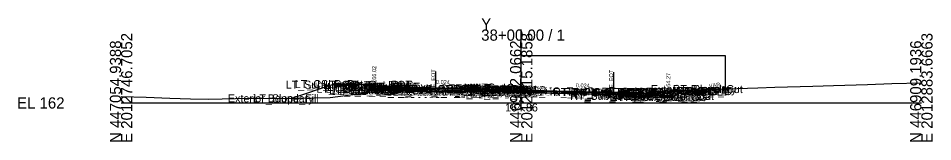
# Model space of a CAD drawing. Extents: x -26 to 3203, y -10 to 9532.
# Drawn here: x 2974.3 to 3202.8, y 1990.3 to 2021.2 of the extents above; entities that cross this region are included whole.
import ezdxf

# ---------------------------------------------------------------- set-up
doc = ezdxf.new("R2010")
doc.units = 0
for name, color, linetype in [('Default', 7, 'Continuous'), ('Exist CMT Pavement', 7, 'Continuous'), ('Exist Cross Section Cell', 7, 'Continuous'), ('Exist XS Center Line Elevation Label', 7, 'Continuous'), ('Exist XS Ground Line', 7, 'Continuous'), ('Prop CMT Conc Surface', 7, 'Continuous'), ('Prop CMT Concrete Structures', 7, 'Continuous'), ('Prop CMT Pvmt Course 1', 7, 'Continuous'), ('Prop CMT Pvmt Course 1 CG', 7, 'Continuous'), ('Prop CMT Pvmt Course 1 Wedge', 7, 'Continuous'), ('Prop CMT Pvmt Course 2', 7, 'Continuous'), ('Prop CMT Pvmt Course 2 Wedge', 7, 'Continuous'), ('Prop CMT Pvmt Course 3', 7, 'Continuous'), ('Prop CMT Pvmt Course 3 Wedge', 7, 'Continuous'), ('Prop CMT Pvmt Surface', 7, 'Continuous'), ('Prop CMT Pvmt Wedge Surface 1', 7, 'Continuous'), ('Prop CMT Pvmt Wedge Surface 2', 7, 'Continuous'), ('Prop CMT Pvmt Wedge Surface 3', 7, 'Continuous'), ('Prop CMT Slope Grass', 7, 'Continuous'), ('Prop CMT Subgrade Earthwork', 7, 'Continuous'), ('Prop XS Finish Grade CurbGutter', 7, 'Continuous'), ('Prop XS Hydro Elevations', 7, 'Continuous'), ('Prop XS Label Text', 7, 'Continuous'), ('Prop XS SE Text', 7, 'Continuous'), ('Prop XS Side Slope Text', 7, 'Continuous'), ('Scratch_Level_0', 7, 'Continuous'), ('Scratch_Level_1', 7, 'Continuous')]:
    doc.layers.add(name, color=color, linetype=linetype)

msp = doc.modelspace()

# ---------------------------------------------------------------- linework, layer by layer
at = {"layer": 'Exist CMT Pavement'}
msp.add_lwpolyline([(3078.61, 2002.84), (3080.82, 2002.84), (3081.52, 2002.84), (3082.19, 2002.84), (3084.44, 2002.85), (3085.61, 2002.85), (3088.05, 2002.86), (3088.93, 2002.86), (3091.69, 2002.86), (3092.4, 2002.86), (3093.85, 2002.86), (3095.41, 2002.86), (3095.88, 2002.86), (3097.36, 2002.86), (3099.69, 2002.86), (3100, 2002.86), (3102.21, 2002.86), (3102.77, 2002.87), (3104.5, 2002.88), (3106.34, 2002.87), (3108.04, 2002.87), (3109.85, 2002.88), (3110.18, 2002.88), (3110.83, 2002.88), (3113.06, 2002.88), (3113.64, 2002.87), (3116.47, 2002.81), (3117.27, 2002.8), (3119.89, 2002.76), (3120.9, 2002.75), (3122.11, 2002.74), (3122.7, 2002.72), (3123.07, 2002.71)], dxfattribs=at)
at = {"layer": 'Exist Cross Section Cell'}
for p, q in [((3100, 2000), (3100, 2018.35)), ((3000, 2000), (3100, 2000)), ((3100, 2000), (3200, 2000))]:
    msp.add_line(p, q, dxfattribs=at)
at = {"layer": 'Exist XS Ground Line'}
msp.add_lwpolyline([(3000, 2001.58), (3006.27, 2001.42), (3012.19, 2001.22), (3017.37, 2001), (3021.88, 2000.95), (3031.97, 2001.15), (3035.6, 2001.19), (3040.92, 2001.1), (3048.27, 2001.29), (3052.24, 2001.36), (3058, 2002.11), (3066.43, 2003.25), (3070.46, 2003.26), (3074.7, 2003.3), (3076.17, 2003.3), (3076.81, 2002.69), (3078.61, 2002.84), (3080.82, 2002.84), (3081.52, 2002.84), (3082.19, 2002.84), (3084.44, 2002.85), (3085.61, 2002.85), (3088.05, 2002.86), (3088.93, 2002.86), (3091.69, 2002.86), (3092.4, 2002.86), (3093.85, 2002.86), (3095.41, 2002.86), (3095.88, 2002.86), (3097.36, 2002.86), (3099.69, 2002.86), (3100, 2002.86), (3102.21, 2002.86), (3102.77, 2002.87), (3104.5, 2002.88), (3106.34, 2002.87), (3108.04, 2002.87), (3109.85, 2002.88), (3110.18, 2002.88), (3110.83, 2002.88), (3113.06, 2002.88), (3113.64, 2002.87), (3116.47, 2002.81), (3117.27, 2002.8), (3119.89, 2002.76), (3120.9, 2002.75), (3122.11, 2002.74), (3122.7, 2002.72), (3123.07, 2002.71), (3124.44, 2002.64), (3124.94, 2002.61), (3125.56, 2003.08), (3127.58, 2003.16), (3129.46, 2003.24), (3132.87, 2003.37), (3133.37, 2002.87), (3142.71, 2003.24), (3147.05, 2003.41), (3148.81, 2003.48), (3159.12, 2003.79), (3163.41, 2003.91), (3172.84, 2004.2), (3178.02, 2004.35), (3186.57, 2004.64), (3192.62, 2004.84), (3200, 2004.99)], dxfattribs=at)
at = {"layer": 'Prop CMT Conc Surface'}
for points in [[(3058.75, 2004.61), (3053.75, 2004.71)], [(3063.25, 2004.02), (3063.25, 2004.52), (3062.75, 2004.52)], [(3065.25, 2004.05), (3063.25, 2004.02)], [(3134.75, 2002.39), (3136.75, 2002.27)], [(3136.75, 2002.27), (3136.75, 2002.77), (3137.25, 2002.77)], [(3141.25, 2002.86), (3146.25, 2002.96)]]:
    msp.add_lwpolyline(points, dxfattribs=at)
at = {"layer": 'Prop CMT Concrete Structures'}
for points in [[(3053.75, 2004.37), (3053.75, 2004.71)], [(3053.75, 2004.71), (3058.75, 2004.61)], [(3058.75, 2004.27), (3053.75, 2004.37)], [(3058.75, 2004.61), (3058.75, 2004.27)], [(3065.25, 2004.05), (3063.25, 2004.02), (3063.25, 2004.52), (3062.75, 2004.52)], [(3062.75, 2004.52), (3062.75, 2003.53), (3065.25, 2003.47)], [(3065.25, 2003.47), (3065.25, 2004.05)], [(3096, 2003.32), (3095.99, 2003.48), (3095.24, 2003.73), (3094, 2003.85), (3092.76, 2003.83), (3092.01, 2003.58), (3092, 2003.41)], [(3092, 2003.41), (3096, 2003.32)], [(3134.75, 2002.39), (3136.75, 2002.27), (3136.75, 2002.77), (3137.25, 2002.77)], [(3137.25, 2002.77), (3137.25, 2001.75), (3134.75, 2001.81)], [(3134.75, 2001.81), (3134.75, 2002.39)], [(3146.25, 2002.96), (3141.25, 2002.86)], [(3141.25, 2002.86), (3141.25, 2002.52)], [(3141.25, 2002.52), (3146.25, 2002.62)], [(3146.25, 2002.62), (3146.25, 2002.96)]]:
    msp.add_lwpolyline(points, dxfattribs=at)
at = {"layer": 'Prop CMT Pvmt Course 1'}
for points in [[(3092, 2003.41), (3065.25, 2004.05)], [(3065.25, 2004.05), (3065.25, 2003.8)], [(3065.25, 2003.8), (3078.61, 2003.48)], [(3088.93, 2003.36), (3092, 2003.29)], [(3092, 2003.41), (3096, 2003.32)], [(3092, 2003.16), (3092, 2003.41)], [(3092, 2003.16), (3092, 2003.41)], [(3092, 2003.29), (3092, 2003.16), (3092, 2003.16)], [(3096, 2003.07), (3092, 2003.16)], [(3096, 2003.32), (3096, 2003.07)], [(3096, 2003.32), (3134.75, 2002.39)], [(3096, 2003.07), (3096, 2003.32)], [(3096, 2003.19), (3096, 2003.07), (3096, 2003.07)], [(3110.18, 2002.85), (3109.12, 2002.88)], [(3110.18, 2002.73), (3110.18, 2002.85)], [(3134.75, 2002.14), (3123.07, 2002.42)], [(3134.75, 2002.39), (3134.75, 2002.14)]]:
    msp.add_lwpolyline(points, dxfattribs=at)
at = {"layer": 'Prop CMT Pvmt Course 1 CG'}
for points in [[(3065.25, 2003.47), (3062.25, 2003.54), (3061.92, 2003.21)], [(3061.92, 2003.21), (3065.25, 2003.13)], [(3065.25, 2003.13), (3065.25, 2003.47)], [(3134.75, 2001.81), (3137.75, 2001.74), (3138.09, 2001.4)], [(3134.75, 2001.48), (3134.75, 2001.81)], [(3138.09, 2001.4), (3134.75, 2001.48)]]:
    msp.add_lwpolyline(points, dxfattribs=at)
at = {"layer": 'Prop CMT Pvmt Course 1 Wedge'}
for points in [[(3092, 2003.29), (3078.61, 2003.61)], [(3109.12, 2002.88), (3110.18, 2002.85)]]:
    msp.add_lwpolyline(points, dxfattribs=at)
at = {"layer": 'Prop CMT Pvmt Course 2'}
for points in [[(3078.61, 2003.48), (3065.25, 2003.8)], [(3065.25, 2003.8), (3065.25, 2003.47)], [(3065.25, 2003.47), (3078.61, 2003.15)], [(3092, 2003.16), (3096, 2003.07)], [(3110.18, 2002.4), (3110.18, 2002.73)], [(3110.18, 2002.73), (3123.07, 2002.42)], [(3134.75, 2001.81), (3123.07, 2002.09)], [(3134.75, 2002.14), (3134.75, 2001.81)]]:
    msp.add_lwpolyline(points, dxfattribs=at)
at = {"layer": 'Prop CMT Pvmt Course 2 Wedge'}
for points in [[(3092, 2003.16), (3088.93, 2003.24)], [(3096, 2003.07), (3104.16, 2002.87)]]:
    msp.add_lwpolyline(points, dxfattribs=at)
at = {"layer": 'Prop CMT Pvmt Course 3'}
for points in [[(3078.61, 2003.15), (3065.25, 2003.47)], [(3065.25, 2003.47), (3065.25, 2003.13)], [(3065.25, 2003.13), (3078.61, 2002.81)], [(3110.18, 2002.4), (3123.07, 2002.09)], [(3134.75, 2001.48), (3123.07, 2001.76)], [(3134.75, 2001.81), (3134.75, 2001.48)]]:
    msp.add_lwpolyline(points, dxfattribs=at)
at = {"layer": 'Prop CMT Pvmt Course 3 Wedge'}
msp.add_lwpolyline([(3090.63, 2002.86), (3088.93, 2002.9)], dxfattribs=at)
at = {"layer": 'Prop CMT Pvmt Surface'}
for points in [[(3092, 2003.41), (3065.25, 2004.05)], [(3092, 2003.41), (3096, 2003.32)], [(3096, 2003.32), (3134.75, 2002.39)]]:
    msp.add_lwpolyline(points, dxfattribs=at)
at = {"layer": 'Prop CMT Pvmt Wedge Surface 1'}
for points in [[(3065.25, 2003.8), (3065.25, 2004.05)], [(3088.93, 2003.24), (3065.25, 2003.8)], [(3092, 2003.29), (3088.93, 2003.36)], [(3088.93, 2003.36), (3088.93, 2003.24)], [(3092, 2003.41), (3092, 2003.16), (3092, 2003.16), (3092, 2003.29)], [(3096, 2003.32), (3096, 2003.07), (3096, 2003.07), (3096, 2003.19)], [(3109.12, 2002.88), (3110.18, 2002.85)], [(3110.18, 2002.85), (3110.18, 2002.73)], [(3110.18, 2002.73), (3123.07, 2002.42)], [(3134.75, 2002.14), (3134.75, 2002.39)]]:
    msp.add_lwpolyline(points, dxfattribs=at)
at = {"layer": 'Prop CMT Pvmt Wedge Surface 2'}
msp.add_line((3096, 2003.07), (3123.07, 2002.42), dxfattribs=at)
for points in [[(3065.25, 2003.8), (3065.25, 2004.05)], [(3088.93, 2003.24), (3065.25, 2003.8)], [(3092, 2003.41), (3092, 2003.16)], [(3096, 2003.32), (3096, 2003.07)], [(3096, 2003.07), (3104.16, 2002.87)], [(3134.75, 2002.14), (3134.75, 2002.39)]]:
    msp.add_lwpolyline(points, dxfattribs=at)
at = {"layer": 'Prop CMT Pvmt Wedge Surface 3'}
for p, q in [((3088.93, 2002.9), (3092, 2002.83)), ((3092, 2002.83), (3123.07, 2002.09))]:
    msp.add_line(p, q, dxfattribs=at)
for points in [[(3065.25, 2003.47), (3065.25, 2004.05)], [(3088.93, 2002.9), (3065.25, 2003.47)], [(3096, 2002.73), (3123.07, 2002.09)], [(3134.75, 2001.81), (3134.75, 2002.39)]]:
    msp.add_lwpolyline(points, dxfattribs=at)
at = {"layer": 'Prop CMT Slope Grass'}
for points in [[(3062.75, 2004.52), (3053.25, 2004.71), (3042.55, 2001.14)], [(3137.25, 2002.77), (3146.25, 2002.95)], [(3146.25, 2002.95), (3146.75, 2002.96), (3150.33, 2003.52)], [(3150.33, 2003.52), (3150.33, 2002.55), (3151, 2002.55), (3151, 2003.54)]]:
    msp.add_lwpolyline(points, dxfattribs=at)
at = {"layer": 'Prop CMT Subgrade Earthwork'}
for p, q in [((3078.61, 2002.81), (3078.61, 2002.84)), ((3123.07, 2001.76), (3123.07, 2002.71))]:
    msp.add_line(p, q, dxfattribs=at)
for points in [[(3065.25, 2003.13), (3061.92, 2003.21), (3060.58, 2004.56)], [(3078.61, 2002.81), (3065.25, 2003.13)], [(3134.75, 2001.48), (3138.09, 2001.4), (3139.51, 2002.81)], [(3123.07, 2001.76), (3134.75, 2001.48)]]:
    msp.add_lwpolyline(points, dxfattribs=at)
at = {"layer": 'Prop XS Finish Grade CurbGutter'}
for p, q in [((3150.33, 2004.04), (3150.53, 2004.04)), ((3150.33, 2004.04), (3151, 2004.04)), ((3150.33, 2004.04), (3150.33, 2003.05)), ((3150.33, 2003.05), (3150.33, 2002.55)), ((3150.33, 2003.05), (3151, 2003.05)), ((3150.33, 2002.55), (3151, 2002.55)), ((3151, 2003.63), (3150.65, 2003.99)), ((3151, 2003.63), (3151, 2003.05)), ((3151, 2003.54), (3151, 2003.54)), ((3151, 2003.05), (3151, 2002.55))]:
    msp.add_line(p, q, dxfattribs=at)
msp.add_arc((3150.53, 2003.88), 0.166, 43.9997, 90, dxfattribs=at)
at = {"layer": 'Prop XS Label Text'}
for p, q in [((3078.61, 2007.84), (3078.61, 2002.84)), ((3123.07, 2007.71), (3123.07, 2002.71))]:
    msp.add_line(p, q, dxfattribs=at)
at = {"layer": 'Scratch_Level_1'}
msp.add_lwpolyline([(3100, 2011.84), (3151, 2011.84), (3151, 2003.54)], dxfattribs=at)

# ---------------------------------------------------------------- texts
at = {"layer": 'Default'}
msp.add_text('-', height=0.0001, dxfattribs=at).set_placement((3000, 2000))
at = {"layer": 'Exist Cross Section Cell'}
for s, p in [('Y', (3090, 2018.35)), ('38+00.00 / 1', (3090, 2015.55)), ('EL 162', (2974, 1998.6))]:
    msp.add_text(s, height=2.8, dxfattribs=at).set_placement(p)
for s, p in [('E 2012746.7052', (3002.8, 1990)), ('E 2012815.1858', (3102.8, 1990)), ('E 2012883.6663', (3202.8, 1990)), ('N 447054.9388', (3000, 1990)), ('N 446982.0662', (3100, 1990)), ('N 446909.1936', (3200, 1990))]:
    msp.add_text(s, height=2.8, rotation=90, dxfattribs=at).set_placement(p)
at = {"layer": 'Exist XS Center Line Elevation Label'}
msp.add_text('164.86', height=2, dxfattribs=at).set_placement((3095.97, 1997.86))
at = {"layer": 'Prop XS Hydro Elevations'}
for s, p in [('166.02', (3063.75, 2005.02)), ('164.27', (3137.25, 2003.27))]:
    msp.add_text(s, height=1, rotation=90, dxfattribs=at).set_placement(p)
at = {"layer": 'Prop XS Label Text'}
for p in [(3078.51, 2003.87), (3122.97, 2003.74)]:
    msp.add_text('E. EOT', height=1, rotation=90, dxfattribs=at).set_placement(p)
at = {"layer": 'Prop XS SE Text'}
for p in [(3078.69, 2004.76), (3113.66, 2003.9)]:
    msp.add_text('0.024', height=1, rotation=358.6359, dxfattribs=at).set_placement(p)
at = {"layer": 'Prop XS Side Slope Text'}
for s, rotation, p in [('3:1', 18.4349, (3046.91, 2003.39)), ('VAR.', 8.9483, (3147, 2003.69))]:
    msp.add_text(s, height=1, rotation=rotation, dxfattribs=at).set_placement(p)
at = {"layer": 'Scratch_Level_0'}
for s, p in [('LT_Sub_Trench_Out_DLT', (3041.14, 2003.56)), ('LT_CSLP_Pnt', (3043.42, 2003.71)), ('LT_CG1_Shelf_Out', (3048.8, 2002.54)), ('LT_CG_Top_Face', (3050.51, 2003.52)), ('LT_CG_Top_BOC', (3051.03, 2003.52)), ('LT_CG_Bot_BOC', (3051.06, 2002.53)), ('LT_CG_Top_Gut', (3051.49, 2003.02)), ('LT_Sub_OEOP', (3052.03, 2002.21)), ('LT_Sub_OEOT_CG', (3052.62, 2002.13)), ('LT_CG_Bot_IE', (3055.16, 2002.47)), ('LT_Sub_OEOT', (3055.33, 2002.13)), ('LT_PV2_OEOT', (3055.42, 2002.8)), ('LT_PV3_OEOT', (3055.42, 2002.47)), ('LT_PV1_OEOT', (3055.99, 2003.05)), ('LT_PV2_OEEOP', (3067.92, 2002.48)), ('LT_PV1_OEEOP', (3068.49, 2002.61)), ('LT_PV1_IEEOP', (3082.52, 2002.29)), ('LT_PV1_PGL', (3083.78, 2002.41)), ('MI_Face In', (3083.9, 2002.58)), ('MI_Top In', (3085.61, 2002.83)), ('MI_Face Out', (3086.26, 2002.48)), ('MI_Top Out', (3086.47, 2002.73)), ('MI_Crown', (3087.07, 2002.85)), ('MI_Bot Out', (3087.26, 2002.32)), ('RT_PV1_PGL', (3087.73, 2002.32)), ('Exterior Boundary', (3132.39, 2002.46)), ('RT_Slope_Cut', (3137.84, 2002.46)), ('Exterior Boundary', (3026.7, 2000.14)), ('LT_Slope_Fill', (3033.07, 2000.14)), ('LT_PV_Sub_Tie_Out', (3063.58, 2001.84)), ('LT_PV_OEEOP_EG', (3066.16, 2001.84)), ('LT_Sub_OEEOP', (3067.83, 2001.81)), ('LT_PV3_OEEOP', (3067.92, 2002.15)), ('LT_PV_EG_TestPt', (3071.72, 2001.85)), ('LT_PV_IEEOP_EG', (3080.19, 2001.86)), ('LT_PV2_IEEOP', (3081.95, 2002.16)), ('LT_PV3_IEEOP', (3081.95, 2001.83)), ('LT_PV2_PGL1', (3082.88, 2002.16)), ('LT_PV3_PGL1', (3082.88, 2001.83)), ('LT_PV2_PGL', (3083.21, 2002.16)), ('LT_PV3_PGL', (3083.21, 2001.83)), ('LT_PV4_PGL', (3083.21, 2001.5)), ('RT_PV_IEEOP_EG', (3084.14, 2001.86)), ('RT_PV2_IEEOP', (3085.91, 2002.07)), ('RT_PV3_IEEOP', (3085.91, 2001.73)), ('RT_PV1_IEEOP', (3086.47, 2002.19)), ('RT_PV2_PGL1', (3086.83, 2002.07)), ('RT_PV3_PGL1', (3086.83, 2001.73)), ('RT_PV2_PGL', (3087.17, 2002.07)), ('RT_PV3_PGL', (3087.17, 2001.73)), ('RT_PV4_PGL', (3087.17, 2001.4)), ('RT_PV_EG_TestPt', (3095.9, 2001.87)), ('RT_PV_Sub_Tie_Out', (3107.96, 2001.71)), ('RT_PV_OEEOP_EG', (3110.57, 2001.71)), ('RT_Sub_OEEOP', (3112.24, 2000.76)), ('RT_PV2_OEEOP', (3112.33, 2001.42)), ('RT_PV3_OEEOP', (3112.33, 2001.09)), ('RT_PV1_OEEOP', (3112.9, 2001.55)), ('RT_Sub_Trench_Out_DLT', (3120.02, 2001.81)), ('RT_Sub_OEOT_CG', (3122.07, 2000.48)), ('RT_CG_Top_Face', (3123.96, 2001.77)), ('RT_CG1_Shelf_Out', (3124.25, 2000.74)), ('RT_CG_Bot_IE', (3124.62, 2000.81)), ('RT_Sub_OEOT', (3124.78, 2000.48)), ('RT_PV2_OEOT', (3124.88, 2001.14)), ('RT_PV3_OEOT', (3124.88, 2000.81)), ('RT_CG_Top_Gut', (3124.94, 2001.27)), ('RT_PV1_OEOT', (3125.44, 2001.39)), ('RT_CG_Top_BOC', (3125.49, 2001.77)), ('RT_CG_Bot_BOC', (3125.52, 2000.75)), ('RT_Sub_OEOP', (3128.15, 2000.4)), ('RT_Shld_O', (3138.79, 2001.95)), ('CSLP_Pnt', (3139.62, 2001.96))]:
    msp.add_text(s, height=2, dxfattribs=at).set_placement(p)

doc.saveas('drawing.dxf')
